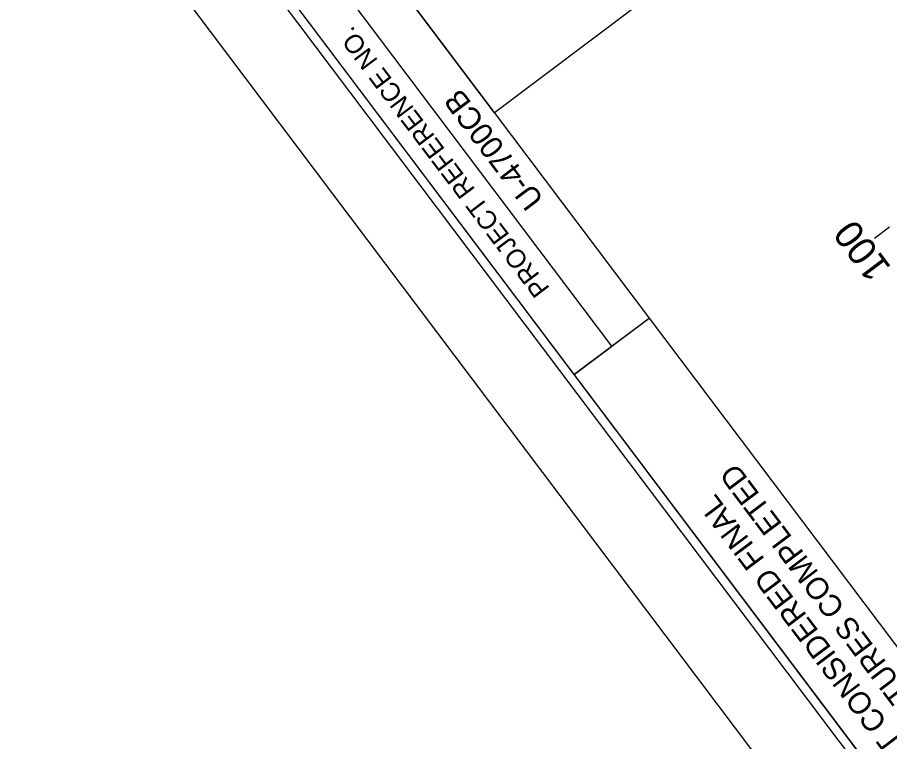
# Model space of a CAD drawing. Extents: x 1263113 to 1265001, y 775064 to 777068.
# Drawn here: x 1263113.4 to 1263346, y 776151.3 to 776344.6 of the extents above; entities that cross this region are included whole.
import ezdxf

# ---------------------------------------------------------------- set-up
doc = ezdxf.new("R2010")
doc.units = 0
for name, color, linetype in [('Sheet Data Field CELL', 7, 'Continuous'), ('Sheet Plan CELL', 7, 'Continuous'), ('Sheet Plot Border Inside CELL', 7, 'Continuous'), ('Sheet Plot Border Outside CELL', 7, 'Continuous'), ('Sheet Sticker Exception Certification CELL', 7, 'Continuous'), ('Sheet Title CELL', 7, 'Continuous'), ('Sheet Typical CELL', 7, 'Continuous')]:
    doc.layers.add(name, color=color, linetype=linetype)

msp = doc.modelspace()

# ---------------------------------------------------------------- linework, layer by layer
at = {"layer": 'Sheet Data Field CELL'}
msp.add_line((1263345.97, 776288.63), (1263341.97, 776285.62), dxfattribs=at)
at = {"layer": 'Sheet Plan CELL'}
msp.add_lwpolyline([(1263251.41, 776491.76), (1263330.45, 776386.82), (1263240.62, 776319.15), (1263161.57, 776424.1)], dxfattribs=at)
at = {"layer": 'Sheet Plot Border Inside CELL'}
msp.add_lwpolyline([(1264977.07, 775721.54), (1263974.73, 777052.27), (1263132.03, 776417.56), (1264134.37, 775086.81)], close=True, dxfattribs=at)
at = {"layer": 'Sheet Plot Border Outside CELL'}
msp.add_lwpolyline([(1263113.35, 776409.12), (1264126.21, 775064.39), (1265000.86, 775723.19), (1263988, 777067.91)], close=True, dxfattribs=at)
at = {"layer": 'Sheet Sticker Exception Certification CELL'}
for p, q in [((1263261.89, 776249.28), (1263281.89, 776264.34)), ((1263281.87, 776264.34), (1263410.06, 776094.15)), ((1263390.06, 776079.1), (1263261.88, 776249.28))]:
    msp.add_line(p, q, dxfattribs=at)
at = {"layer": 'Sheet Title CELL'}
msp.add_line((1263345.98, 776288.62), (1263341.99, 776285.62), dxfattribs=at)
at = {"layer": 'Sheet Typical CELL'}
for p, q in [((1263281.92, 776264.37), (1263161.57, 776424.15)), ((1263271.91, 776256.83), (1263151.56, 776416.61)), ((1263261.89, 776249.28), (1263141.54, 776409.07)), ((1264044, 775210.92), (1263141.54, 776409.07)), ((1263281.92, 776264.37), (1263261.89, 776249.28))]:
    msp.add_line(p, q, dxfattribs=at)

# ---------------------------------------------------------------- texts
at = {"layer": 'Sheet Data Field CELL'}
for s, height, p in [('U-4700CB', 6, (1263253.98, 776296.04)), ('100', 7.488, (1263346.6, 776277.82))]:
    msp.add_text(s, height=height, rotation=126.9874, dxfattribs=at).set_placement(p)
at = {"layer": 'Sheet Plan CELL'}
msp.add_text('PROJECT REFERENCE NO.', height=5.0001, rotation=126.9874, dxfattribs=at).set_placement((1263255.5, 776272.25))
at = {"layer": 'Sheet Sticker Exception Certification CELL'}
for s, p in [('UNLESS ALL SIGNATURES COMPLETED', (1263396.1, 776104.98)), ('DOCUMENT NOT CONSIDERED FINAL', (1263385.36, 776103.65))]:
    msp.add_text(s, height=5.8579, rotation=126.9874, dxfattribs=at).set_placement(p)

doc.saveas('drawing.dxf')
